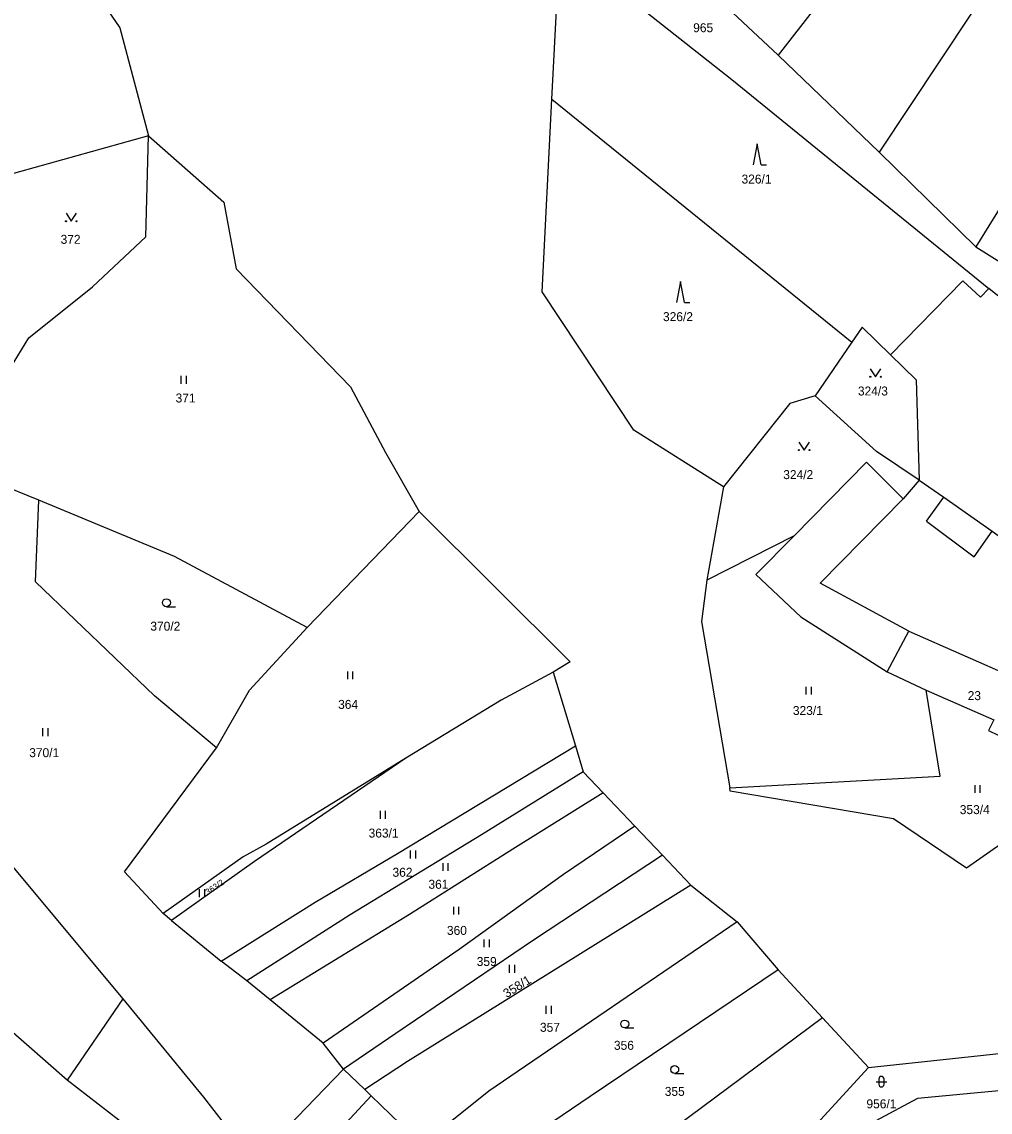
# Model space of a CAD drawing. Extents: x -7483133 to -743169, y -11317770 to -1127091.
# Drawn here: x -747956.4 to -747772.5, y -1130852.2 to -1130645.3 of the extents above; entities that cross this region are included whole.
import ezdxf

# ---------------------------------------------------------------- set-up
doc = ezdxf.new("R2010")
doc.units = 0
for name, color, linetype in [('Hranice parcel', 7, 'Continuous'), ('Parcelní čísla', 7, 'Continuous'), ('Vnitřní kresba', 7, 'Continuous'), ('Značky kultur', 7, 'Continuous')]:
    doc.layers.add(name, color=color, linetype=linetype)

msp = doc.modelspace()

# ---------------------------------------------------------------- linework, layer by layer
at = {"layer": 'Hranice parcel'}
for p, q in [((-747855.76, -1130660), (-747854.2, -1130630.54)), ((-747793.6, -1130670.03), (-747812.8, -1130651.64)), ((-747855.76, -1130660), (-747798.81, -1130706.12)), ((-747932.35, -1130666.92), (-747959.56, -1130674.56)), ((-747775.28, -1130688.03), (-747793.6, -1130670.03)), ((-747798.81, -1130706.12), (-747805.74, -1130716.29)), ((-747953.15, -1130736.09), (-747968.32, -1130729.96)), ((-747823.18, -1130733.56), (-747826.34, -1130751.29)), ((-747880.96, -1130738.26), (-747902.23, -1130760.25)), ((-747809.75, -1130742.85), (-747826.34, -1130751.29)), ((-747855.52, -1130768.71), (-747851.3, -1130782.72)), ((-747985.28, -1130773.23), (-747937.23, -1130830.7)), ((-747851.3, -1130782.72), (-747849.81, -1130787.66)), ((-747849.81, -1130787.66), (-747846.02, -1130791.65)), ((-747846.02, -1130791.65), (-747840.01, -1130797.96)), ((-747840.01, -1130797.96), (-747834.77, -1130803.46)), ((-747834.77, -1130803.46), (-747829.36, -1130809.14)), ((-747829.36, -1130809.14), (-747820.55, -1130816.09)), ((-747927.97, -1130815.84), (-747929.55, -1130814.55)), ((-747927.97, -1130815.84), (-747918.56, -1130823.54)), ((-747820.55, -1130816.09), (-747812.81, -1130825.22)), ((-747913.69, -1130827.28), (-747918.56, -1130823.54)), ((-747812.81, -1130825.22), (-747804.38, -1130834.32)), ((-747909.27, -1130830.92), (-747913.69, -1130827.28)), ((-747937.23, -1130830.7), (-747947.78, -1130846.14)), ((-747899.19, -1130839.1), (-747909.27, -1130830.92)), ((-747804.38, -1130834.32), (-747840.03, -1130860.79)), ((-747804.38, -1130834.32), (-747795.63, -1130843.76)), ((-747895.31, -1130844.05), (-747899.19, -1130839.1)), ((-747891.29, -1130847.94), (-747895.31, -1130844.05))]:
    msp.add_line(p, q, dxfattribs=at)
for points in [[(-747670.88, -1130391.23), (-747687.06, -1130427.38), (-747690.77, -1130434.65), (-747700.47, -1130450.94), (-747706.19, -1130460.89), (-747729.37, -1130504.92), (-747757.72, -1130558.53), (-747788.4, -1130617.12), (-747798.54, -1130633.27), (-747812.8, -1130651.64)], [(-747640.79, -1130396.7), (-747657.25, -1130425.6), (-747681.35, -1130469.07), (-747696.46, -1130497.05), (-747715.13, -1130532.2), (-747745.26, -1130590.19), (-747770.48, -1130635.15), (-747793.6, -1130670.03)], [(-747623.29, -1130422.15), (-747647.06, -1130457.06), (-747666.03, -1130492.64), (-747685.16, -1130527.86), (-747701.96, -1130558.66), (-747718.97, -1130592.94), (-747735.96, -1130622.98), (-747758.49, -1130660.91), (-747775.28, -1130688.03)], [(-747812.8, -1130651.64), (-747826.2, -1130639.05), (-747848.84, -1130625.02)], [(-747948.65, -1130630.54), (-747937.8, -1130646.48), (-747932.35, -1130666.92)], [(-747854.2, -1130630.54), (-747821.59, -1130656.28), (-747772.81, -1130695.9)], [(-747823.18, -1130733.56), (-747840.23, -1130722.79), (-747857.62, -1130696.55), (-747855.76, -1130660)], [(-747965.59, -1130718.16), (-747963.47, -1130718.96), (-747955.1, -1130705.31), (-747942.97, -1130695.63), (-747932.86, -1130686.09), (-747932.35, -1130666.92)], [(-747932.35, -1130666.92), (-747918.04, -1130679.51), (-747915.7, -1130692.18), (-747894.02, -1130714.58), (-747887.33, -1130727.05), (-747880.96, -1130738.26)], [(-747775.28, -1130688.03), (-747758.65, -1130698.41), (-747747.98, -1130702.67)], [(-747772.81, -1130695.9), (-747774.39, -1130697.56), (-747777.71, -1130694.48), (-747791.49, -1130708.53)], [(-747753.68, -1130704.39), (-747771.13, -1130697.26), (-747772.81, -1130695.9)], [(-747791.49, -1130708.53), (-747796.84, -1130703.24), (-747798.81, -1130706.12)], [(-747791.49, -1130708.53), (-747786.57, -1130713.25), (-747786.02, -1130732.27)], [(-747805.74, -1130716.29), (-747810.6, -1130717.76), (-747823.18, -1130733.56)], [(-747786.02, -1130732.27), (-747794.12, -1130726.84), (-747805.74, -1130716.29)], [(-747786.02, -1130732.27), (-747789.07, -1130735.84), (-747796.03, -1130728.88), (-747809.75, -1130742.85)], [(-747786.02, -1130732.27), (-747781.34, -1130735.54), (-747772.13, -1130741.97), (-747766.72, -1130745.89), (-747759.19, -1130751.34), (-747749.2, -1130758.56)], [(-747919.46, -1130783.07), (-747931.23, -1130773.21), (-747953.83, -1130751.57), (-747953.15, -1130736.09)], [(-747902.23, -1130760.25), (-747927.4, -1130746.77), (-747953.15, -1130736.09)], [(-747880.96, -1130738.26), (-747852.28, -1130766.74), (-747855.52, -1130768.71)], [(-747809.75, -1130742.85), (-747817.01, -1130750.2), (-747808.52, -1130758.22), (-747792.09, -1130768.69), (-747784.71, -1130772.17)], [(-747826.34, -1130751.29), (-747827.34, -1130759.1), (-747822, -1130790.67)], [(-747919.46, -1130783.07), (-747913.2, -1130772.11), (-747902.23, -1130760.25)], [(-747855.52, -1130768.71), (-747865.41, -1130774.06), (-747883.52, -1130785.07)], [(-747822, -1130790.67), (-747782.01, -1130788.46), (-747784.71, -1130772.17)], [(-747784.71, -1130772.17), (-747771.86, -1130777.78), (-747772.86, -1130779.79), (-747771.01, -1130780.65)], [(-747929.55, -1130814.55), (-747936.92, -1130806.6), (-747919.46, -1130783.07)], [(-747918.56, -1130823.54), (-747900.68, -1130812.35), (-747885.1, -1130803.15), (-747851.3, -1130782.72)], [(-747883.52, -1130785.07), (-747910.03, -1130801.35), (-747914.38, -1130803.79), (-747929.55, -1130814.55)], [(-747883.52, -1130785.07), (-747912.25, -1130804.68), (-747927.97, -1130815.84)], [(-747849.81, -1130787.66), (-747869.15, -1130799.59), (-747894.06, -1130814.79), (-747913.69, -1130827.28)], [(-747754.53, -1130790.17), (-747777.03, -1130805.89), (-747790.88, -1130796.57), (-747821.89, -1130791.29), (-747822, -1130790.67)], [(-747846.02, -1130791.65), (-747863.17, -1130802.29), (-747882.81, -1130814.71), (-747909.27, -1130830.92)], [(-747840.01, -1130797.96), (-747853.58, -1130807.15), (-747873.39, -1130821.38), (-747899.19, -1130839.1)], [(-747834.77, -1130803.46), (-747859.22, -1130819.6), (-747885.37, -1130837.32), (-747895.31, -1130844.05)], [(-747947.78, -1130846.14), (-747959.65, -1130835.75), (-748001.98, -1130807.92)], [(-747829.36, -1130809.14), (-747883.17, -1130842.59), (-747891.29, -1130847.94)], [(-747820.55, -1130816.09), (-747867.74, -1130848.23), (-747880.46, -1130858.39)], [(-747812.81, -1130825.22), (-747848.46, -1130849.27), (-747866.39, -1130861.37), (-747873.03, -1130866.5)], [(-747795.63, -1130843.76), (-747754.3, -1130839.33), (-747742.68, -1130830.62), (-747726.57, -1130826.97)], [(-747937.23, -1130830.7), (-747921.89, -1130849.4), (-747917.99, -1130854.46), (-747911.17, -1130860.49), (-747903.93, -1130864)], [(-747895.31, -1130844.05), (-747909.44, -1130858.68), (-747903.93, -1130864)], [(-747831.64, -1130880.59), (-747825.65, -1130878.15), (-747808.21, -1130857.46), (-747795.63, -1130843.76)], [(-747931.2, -1130863.28), (-747934.04, -1130856.8), (-747947.78, -1130846.14)], [(-747751.43, -1130846.33), (-747786.35, -1130849.61), (-747800.53, -1130857.22), (-747810.62, -1130866.79), (-747823.91, -1130884.54), (-747825.73, -1130887.83)], [(-747880.46, -1130858.39), (-747882.73, -1130856.2), (-747890.05, -1130849.13), (-747891.29, -1130847.94)]]:
    msp.add_lwpolyline(points, dxfattribs=at)
at = {"layer": 'Vnitřní kresba'}
for p, q in [((-747804.85, -1130751.83), (-747789.07, -1130735.84)), ((-747784.64, -1130740.08), (-747781.34, -1130735.54)), ((-747784.64, -1130740.08), (-747775.61, -1130746.82)), ((-747775.61, -1130746.82), (-747772.13, -1130741.97)), ((-747787.96, -1130760.97), (-747804.85, -1130751.83)), ((-747792.09, -1130768.69), (-747787.96, -1130760.97)), ((-747787.96, -1130760.97), (-747758.9, -1130773.71)), ((-747890.05, -1130849.13), (-747897.92, -1130857.56))]:
    msp.add_line(p, q, dxfattribs=at)
at = {"layer": 'Značky kultur'}
for p, q in [((-747816.78, -1130668.45), (-747817.53, -1130672.45)), ((-747816.03, -1130672.45), (-747816.78, -1130668.45)), ((-747816.03, -1130672.45), (-747815.03, -1130672.45)), ((-747831.32, -1130694.56), (-747832.07, -1130698.56)), ((-747830.57, -1130698.56), (-747831.32, -1130694.56)), ((-747830.57, -1130698.56), (-747829.57, -1130698.56)), ((-747926.16, -1130714), (-747926.16, -1130712.5)), ((-747925.16, -1130714), (-747925.16, -1130712.5)), ((-747928.95, -1130756.3), (-747927.2, -1130756.3)), ((-747894.53, -1130770.07), (-747894.53, -1130768.57)), ((-747893.53, -1130770.07), (-747893.53, -1130768.57)), ((-747807.48, -1130772.98), (-747807.48, -1130771.48)), ((-747806.48, -1130772.98), (-747806.48, -1130771.48)), ((-747952.41, -1130780.84), (-747952.41, -1130779.34)), ((-747951.41, -1130780.84), (-747951.41, -1130779.34)), ((-747775.41, -1130791.65), (-747775.41, -1130790.15)), ((-747774.41, -1130791.65), (-747774.41, -1130790.15)), ((-747888.33, -1130796.55), (-747888.33, -1130795.05)), ((-747887.33, -1130796.55), (-747887.33, -1130795.05)), ((-747882.59, -1130804.06), (-747882.59, -1130802.56)), ((-747881.59, -1130804.06), (-747881.59, -1130802.56)), ((-747876.43, -1130806.45), (-747876.43, -1130804.95)), ((-747875.43, -1130806.45), (-747875.43, -1130804.95)), ((-747922.64, -1130811.41), (-747922.64, -1130809.91)), ((-747921.64, -1130811.41), (-747921.64, -1130809.91)), ((-747874.4, -1130814.73), (-747874.4, -1130813.23)), ((-747873.4, -1130814.73), (-747873.4, -1130813.23)), ((-747868.61, -1130820.93), (-747868.61, -1130819.43)), ((-747867.61, -1130820.93), (-747867.61, -1130819.43)), ((-747863.81, -1130825.77), (-747863.81, -1130824.27)), ((-747862.81, -1130825.77), (-747862.81, -1130824.27)), ((-747856.86, -1130833.54), (-747856.86, -1130832.04)), ((-747855.86, -1130833.54), (-747855.86, -1130832.04)), ((-747841.92, -1130836.24), (-747840.17, -1130836.24)), ((-747832.44, -1130844.88), (-747830.69, -1130844.88)), ((-747794.18, -1130846.44), (-747792.18, -1130846.44)), ((-747793.68, -1130845.94), (-747793.68, -1130846.94)), ((-747792.68, -1130846.94), (-747792.68, -1130845.94))]:
    msp.add_line(p, q, dxfattribs=at)
for points in [[(-747948.01, -1130681.65), (-747947.01, -1130683.15), (-747946.01, -1130681.65)], [(-747795.3, -1130711.17), (-747794.3, -1130712.67), (-747793.3, -1130711.17)], [(-747808.86, -1130725.08), (-747807.86, -1130726.58), (-747806.86, -1130725.08)]]:
    msp.add_lwpolyline(points, dxfattribs=at)
for centre, radius in [((-747948.01, -1130683.15), 0.1), ((-747946.01, -1130683.15), 0.1), ((-747795.3, -1130712.67), 0.1), ((-747793.3, -1130712.67), 0.1), ((-747808.86, -1130726.58), 0.1), ((-747806.86, -1130726.58), 0.1), ((-747928.95, -1130755.55), 0.75), ((-747841.92, -1130835.49), 0.75), ((-747832.44, -1130844.13), 0.75)]:
    msp.add_circle(centre, radius, dxfattribs=at)
for centre, start, end in [((-747793.18, -1130845.94), 0, 180), ((-747793.18, -1130846.94), 180, 359.9879)]:
    msp.add_arc(centre, 0.5, start, end, dxfattribs=at)

# ---------------------------------------------------------------- texts
at = {"layer": 'Parcelní čísla'}
for s, p in [('965', (-747828.93, -1130647.28)), ('326/1', (-747819.75, -1130676)), ('372', (-747949.04, -1130687.44)), ('326/2', (-747834.66, -1130702.11)), ('371', (-747927.21, -1130717.55)), ('324/3', (-747797.65, -1130716.22)), ('324/2', (-747811.83, -1130732.09)), ('370/2', (-747932, -1130760.85)), ('364', (-747896.35, -1130775.69)), ('23', (-747776.81, -1130774.03)), ('323/1', (-747810, -1130776.85)), ('370/1', (-747955, -1130784.85)), ('353/4', (-747778.31, -1130795.66)), ('363/1', (-747890.56, -1130800.11)), ('362', (-747886.02, -1130807.55)), ('361', (-747879.2, -1130809.83)), ('360', (-747875.69, -1130818.58)), ('359', (-747870.03, -1130824.48)), ('357', (-747858.02, -1130836.97)), ('356', (-747843.98, -1130840.39)), ('355', (-747834.33, -1130849.13)), ('956/1', (-747796.03, -1130851.49))]:
    msp.add_text(s, height=1.7, dxfattribs=at).set_placement(p)
for s, height, rotation, p in [('363/2', 1.14, 34, (-747921.06, -1130811.04)), ('358/1', 1.7, 32, (-747864.34, -1130830.6))]:
    msp.add_text(s, height=height, rotation=rotation, dxfattribs=at).set_placement(p)

doc.saveas('drawing.dxf')
